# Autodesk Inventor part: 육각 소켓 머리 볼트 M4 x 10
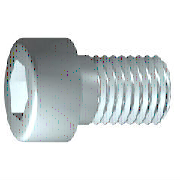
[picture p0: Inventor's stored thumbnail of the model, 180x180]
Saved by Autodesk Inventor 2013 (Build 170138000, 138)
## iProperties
IsCustomPart: 1
Created: 2012-02
Part Number: 육각 소켓 머리 볼트 M4 x 10
Material: 스테인리스강
Description: 6각 소켓 머리 캡 나사
Document SubType Name: Modeling
Standard: ISO 4762
Designer: mduedu
Standard Revision: Fourth edition 2004-03-01
Standards Organization: ISO
Language: ko-KR
Size Designation: M4 x 10
Categories: <MemberInstance><Categories><Category DisplayName="조임쇠" InternalName="e4da775c-781d-43d5-af7c-5136215cf5a6" Mnemonic="FSTN"><Category DisplayName="볼트" InternalN
Density: 8.08 g/cm^3
Mass: 2.09412 g
Surface Area: 3.0572 cm^2
Volume: 0.259174 cm^3
Author: mduedu
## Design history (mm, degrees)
sketch "스케치1"
  geometry: L1 (-1, 0)-(10, 0); L2 (10, 0)-(10, 2); L3 (10, 2)-(1.75, 2); L4 (1.75, 2)-(1.32, 2); L5 (1.32, 2)-(0, 2); L6 (0, 2)-(0, 3.5); L7 (0, 3.5)-(-4, 3.5); L8 (-4, 3.5)-(-4, 1.732); L9 (-4, 1.732)-(-2, 1.732); L10 (-2, 1.732)-(-1, 0); L11 (-6.8, 0)-(12.8, 0) reference; L12 (0, -0.7)-(0, 4.2) reference; L13 (1.75, 2)-(0, 2)
  constraints: 22 end point, 6 parallel, 2 collinear, 2 perpendicular, 1 horizontal, 1 point on line
  dimensions: "d1" = 8.25 distance from line of L3.end L2 (= GEL); "d2" = 0.42952 distance of L4.end L3.end (computed from GAL); "d3" = 4 distance between parallel lines of L8 L6 (= KOH); "d4" = 2 distance of L8.end L9.end (= INTI); "d5" = 60 deg angle of L10 L1; "d6" = 4 diameter of L3 L1 (= GD); "d7" = 4 diameter of L5 L1 (= BDM); "d8" = 3.4641 diameter of L9 L1 (= 1.1547 x SW); "d9" = 7 diameter of L7 L1 (= KOD); "d26" = 10 distance between parallel lines of L12 L2 (= NLG)
revolve "본체" sketch "스케치1" stored, may be unused: angle "d10" = 90 deg
sketch "스케치2"
  geometry: L1 (0, -4.9)-(0, 4.9) reference; L2 (-4.9, 0)-(4.9, 0) reference; L3 (1.732, 0)-(0.866, -1.5); L4 (0.866, -1.5)-(-0.866, -1.5); L5 (-0.866, -1.5)-(-1.732, 0); L6 (-1.732, 0)-(-0.866, 1.5); L7 (-0.866, 1.5)-(0.866, 1.5); L8 (0.866, 1.5)-(1.732, 0); 2 further points
  constraints: 12 end point, 1 coincident, 1 horizontal alignment, 1 point on line, 12 other
extrude "슬롯" join sketch "스케치2" stored distance "d11" = 10; taper "d12" = 0 deg
workplane "Work Plane1"
fillet "Fillet2" dims "d30" = 0.1 (= R)
body "Solid1"
fillet "모깎기1" dims "d17" = 0.4 (= RR)
feature "스레드" dims "d13" = 8.25 (= GEL), "d14" = 0
chamfer "모따기1" distance "d15" = 0.42941 (= -0.5 x SPD + 0.5 x GD); stored, may be unused: second distance "d16" = 0.42941 (= GUL), angle "d27" = 45 deg
other parameters: "GD" = 4 [user parameter; used in 2 equation terms], "NLG" = 10 [user parameter; used in 1 equation term], "GEL" = 8.25 [user parameter; used in 2 equation terms], "KOD" = 7 [user parameter; used in 1 equation term], "KOH" = 4 [user parameter; used in 1 equation term], "INTI" = 2 [user parameter; used in 1 equation term], "GAL" = 0.42941 (= 0.61345 x PTC) [user parameter; used in 1 equation term], "GUL" = 0.42941 (= 0.61345 x PTC) [user parameter; used in 1 equation term], "BDM" = 4 (= NND) [user parameter; used in 1 equation term], "SW" = 3 [user parameter; used in 2 equation terms], "RR" = 0.4 [user parameter; used in 1 equation term], "SPD" = 3.14117 (= NND - 1.2269 x PTC) [user parameter; used in 1 equation term], "d19" = 0, "d28" = 0, "d29" = 0, "R" = 0.1 [user parameter; used in 1 equation term], "TOA" = 30 deg [user parameter], "GD1" = 3.14117 (= THREADDIA - 1.2269 x PTC) [user parameter], "THREADDIA" = 4 [user parameter; used in 1 equation term], "FAWI" = 45 deg [user parameter], "TPU" = 14.28571 (computed from PTC) [user parameter], "PTC" = 0.7 [user parameter; used in 5 equation terms], "NND" = 4 [user parameter; used in 2 equation terms], "E0" = 3.465 (= 1.155 x SW) [user parameter]
